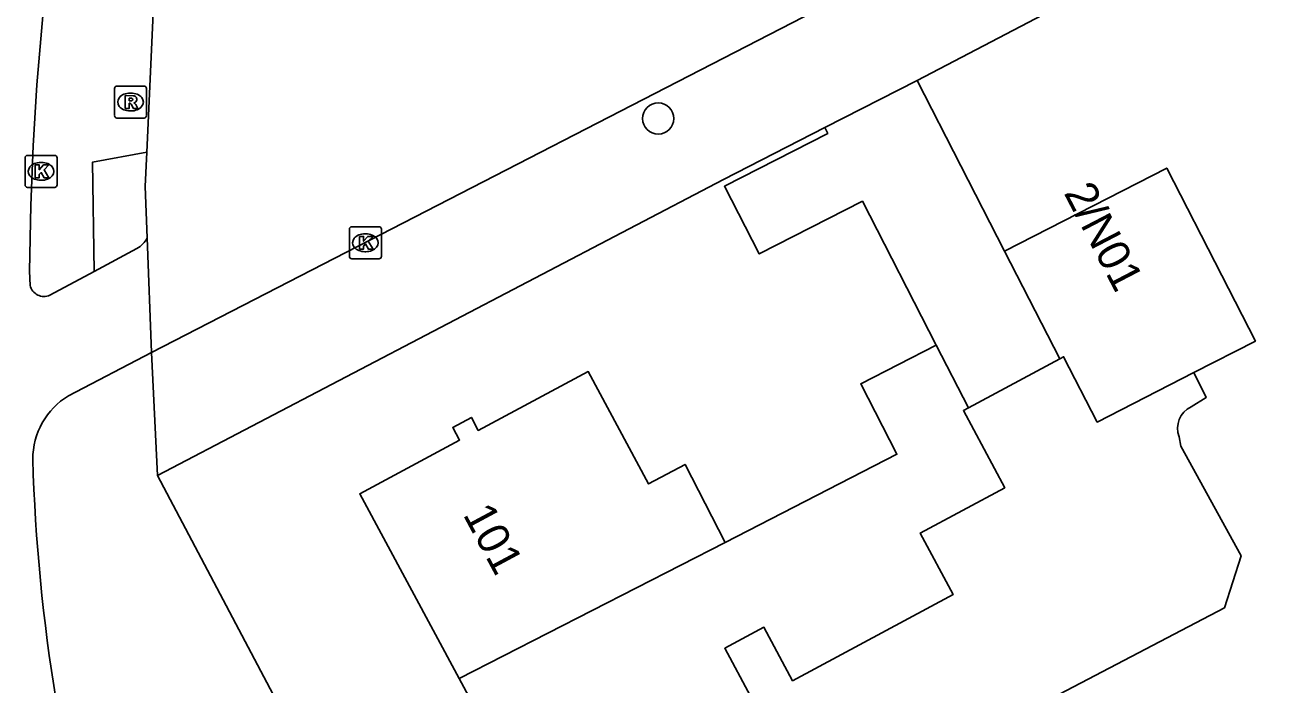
# Model space of a CAD drawing. Extents: x 162880 to 165536, y 384011 to 385179.
# Drawn here: x 162927.6 to 162966.79, y 384170.7 to 384191.34 of the extents above; entities that cross this region are included whole.
import ezdxf

# ---------------------------------------------------------------- set-up
doc = ezdxf.new("R2010")
doc.units = 0
for name, color, linetype in [('IMGEO_Boom', 7, 'Continuous'), ('IMGEO_Fietspad_open', 7, 'Continuous'), ('IMGEO_Groenvoorziening', 7, 'Continuous'), ('IMGEO_Kolk', 7, 'Continuous'), ('IMGEO_Pand', 7, 'Continuous'), ('IMGEO_Pand_nummerreeks', 7, 'Continuous'), ('IMGEO_Rijbaan_lokaal_open', 7, 'Continuous'), ('IMGEO_Rioolput', 7, 'Continuous'), ('IMGEO_Voetpad_open', 7, 'Continuous')]:
    doc.layers.add(name, color=color, linetype=linetype)

msp = doc.modelspace()

# ---------------------------------------------------------------- linework, layer by layer
at = {"layer": 'IMGEO_Boom'}
msp.add_circle((162947.388, 384188.412), 0.489, dxfattribs=at)
at = {"layer": 'IMGEO_Fietspad_open'}
for points in [[(162927.759, 384183.194), (162927.739, 384183.64), (162927.779, 384185.695), (162927.846, 384187.562), (162927.96, 384189.468), (162928.193, 384192.099)], [(162929.751, 384183.633), (162931.087, 384184.349)], [(162929.751, 384183.633), (162928.37, 384182.892)], [(162931.553, 384181.098), (162928.956, 384179.741)]]:
    msp.add_lwpolyline(points, dxfattribs=at)
for centre, radius, start, end in [((162930.781, 384184.976), 0.697, 296.0123, 335.3683), ((162928.181, 384183.279), 0.431, 191.4134, 295.9829), ((162930.134, 384177.77), 2.296, 120.8634, 180.4074), ((162984.182, 384179.392), 56.368, 181.6649, 197.079)]:
    msp.add_arc(centre, radius, start, end, dxfattribs=at)
at = {"layer": 'IMGEO_Groenvoorziening'}
for points in [[(162964.134, 384180.467), (162964.511, 384179.684), (162964.05, 384179.396)], [(162963.675, 384178.458), (162963.724, 384178.168), (162965.607, 384174.74), (162965.09, 384173.113), (162951.391, 384165.934), (162950.819, 384165.634), (162952.828, 384161.829), (162942.595, 384156.45)]]:
    msp.add_lwpolyline(points, dxfattribs=at)
msp.add_arc((162964.352, 384178.731), 0.73, 114.4429, 201.9753, dxfattribs=at)
at = {"layer": 'IMGEO_Kolk'}
for p, q in [((162927.596, 384186.334), (162927.596, 384187.186)), ((162927.671, 384187.26), (162928.523, 384187.26)), ((162928.597, 384187.186), (162928.597, 384186.334)), ((162928.084, 384187.04), (162928.109, 384187.04)), ((162928.107, 384186.48), (162928.082, 384186.48)), ((162928.523, 384186.26), (162927.671, 384186.26)), ((162937.734, 384184.102), (162937.734, 384184.954)), ((162937.809, 384185.028), (162938.661, 384185.028)), ((162938.222, 384184.808), (162938.247, 384184.808)), ((162938.735, 384184.954), (162938.735, 384184.102)), ((162938.661, 384184.028), (162937.809, 384184.028)), ((162938.245, 384184.248), (162938.22, 384184.248))]:
    msp.add_line(p, q, dxfattribs=at)
for points in [[(162927.596, 384186.334), (162927.596, 384187.186)], [(162927.671, 384187.26), (162928.523, 384187.26)], [(162928.597, 384187.186), (162928.597, 384186.334)], [(162927.917, 384186.96), (162928.04, 384186.96), (162928.04, 384186.809), (162928.17, 384186.96), (162928.334, 384186.96), (162928.188, 384186.809), (162928.341, 384186.56), (162928.189, 384186.56), (162928.104, 384186.724), (162928.04, 384186.657), (162928.04, 384186.56), (162927.917, 384186.56), (162927.917, 384186.96)], [(162928.523, 384186.26), (162927.671, 384186.26)], [(162937.734, 384184.102), (162937.734, 384184.954)], [(162937.809, 384185.028), (162938.661, 384185.028)], [(162938.735, 384184.954), (162938.735, 384184.102)], [(162938.055, 384184.728), (162938.178, 384184.728), (162938.178, 384184.577), (162938.308, 384184.728), (162938.472, 384184.728), (162938.326, 384184.577), (162938.479, 384184.328), (162938.327, 384184.328), (162938.242, 384184.492), (162938.178, 384184.425), (162938.178, 384184.328), (162938.055, 384184.328), (162938.055, 384184.728)], [(162938.661, 384184.028), (162937.809, 384184.028)]]:
    msp.add_lwpolyline(points, dxfattribs=at)
for centre, start, end in [((162927.673, 384187.184), 91.552, 178.448), ((162927.673, 384187.184), 91.552, 178.448), ((162928.521, 384187.184), 1.552, 88.448), ((162928.521, 384187.184), 1.552, 88.448), ((162927.673, 384186.336), 181.552, 268.448), ((162927.673, 384186.336), 181.552, 268.448), ((162928.521, 384186.336), 271.552, 358.448), ((162928.521, 384186.336), 271.552, 358.448), ((162937.811, 384184.952), 91.552, 178.448), ((162937.811, 384184.952), 91.552, 178.448), ((162938.659, 384184.952), 1.552, 88.448), ((162938.659, 384184.952), 1.552, 88.448), ((162937.811, 384184.104), 181.552, 268.448), ((162937.811, 384184.104), 181.552, 268.448), ((162938.659, 384184.104), 271.552, 358.448), ((162938.659, 384184.104), 271.552, 358.448)]:
    msp.add_arc(centre, 0.0765, start, end, dxfattribs=at)
for centre, major_axis, ratio, start_param, end_param in [((162928.083, 384186.76), (-0.387, 0.002), 0.722429, 4.712389, 7.853982), ((162928.108, 384186.76), (-0.39, 0.002), 0.717154, 1.570796, 4.712389), ((162938.221, 384184.528), (-0.387, 0.002), 0.722429, 4.712389, 7.853982), ((162938.246, 384184.528), (-0.39, 0.002), 0.717154, 1.570796, 4.712389)]:
    msp.add_ellipse(centre, major_axis=major_axis, ratio=ratio, start_param=start_param, end_param=end_param, dxfattribs=at)
at = {"layer": 'IMGEO_Pand'}
for points in [[(162952.594, 384188.127), (162955.477, 384189.605)], [(162955.477, 384189.605), (162958.214, 384184.265)], [(162952.594, 384188.127), (162952.685, 384187.949), (162949.459, 384186.296), (162950.545, 384184.176), (162953.772, 384185.828), (162956.078, 384181.328)], [(162958.214, 384184.265), (162963.283, 384186.864), (162965.008, 384183.5), (162966.057, 384181.453), (162964.134, 384180.467)], [(162959.939, 384180.899), (162958.214, 384184.265)], [(162949.476, 384175.158), (162954.851, 384177.912), (162953.72, 384180.119), (162956.078, 384181.328)], [(162956.078, 384181.328), (162957.085, 384179.365)], [(162957.085, 384179.365), (162959.939, 384180.899)], [(162964.134, 384180.467), (162961.109, 384178.917), (162960.06, 384180.964), (162959.939, 384180.899)], [(162941.166, 384170.898), (162938.06, 384176.678), (162941.178, 384178.354), (162940.965, 384178.751), (162941.547, 384179.063), (162941.764, 384178.657), (162945.201, 384180.5), (162947.086, 384176.985), (162948.226, 384177.596), (162949.476, 384175.158)], [(162957.085, 384179.365), (162956.925, 384179.279), (162958.221, 384176.868), (162955.578, 384175.448), (162956.61, 384173.527), (162951.589, 384170.83), (162950.69, 384172.503), (162949.466, 384171.845), (162951.077, 384168.848), (162944.242, 384165.175), (162941.166, 384170.898)], [(162941.166, 384170.898), (162949.476, 384175.158)]]:
    msp.add_lwpolyline(points, dxfattribs=at)
at = {"layer": 'IMGEO_Rijbaan_lokaal_open'}
for points in [[(162931.706, 384194.016), (162931.403, 384187.357)], [(162956.944, 384194.183), (162931.553, 384181.098)], [(162931.415, 384184.685), (162931.354, 384186.287), (162931.403, 384187.357)], [(162931.553, 384181.098), (162931.415, 384184.685)]]:
    msp.add_lwpolyline(points, dxfattribs=at)
at = {"layer": 'IMGEO_Rioolput'}
for p, q in [((162930.391, 384188.502), (162930.391, 384189.354)), ((162930.466, 384189.428), (162931.318, 384189.428)), ((162930.879, 384189.208), (162930.904, 384189.208)), ((162931.392, 384189.354), (162931.392, 384188.502)), ((162931.318, 384188.428), (162930.466, 384188.428)), ((162930.902, 384188.648), (162930.877, 384188.648))]:
    msp.add_line(p, q, dxfattribs=at)
for points in [[(162930.391, 384188.502), (162930.391, 384189.354)], [(162930.466, 384189.428), (162931.318, 384189.428)], [(162930.98, 384189.126), (162930.728, 384189.128), (162930.728, 384188.728)], [(162931.392, 384189.354), (162931.392, 384188.502)], [(162930.728, 384188.728), (162930.852, 384188.728), (162930.852, 384188.89), (162930.863, 384188.89)], [(162930.906, 384189.047), (162930.852, 384189.047), (162930.852, 384188.966)], [(162930.852, 384188.966), (162930.904, 384188.966)], [(162930.91, 384188.861), (162930.981, 384188.728), (162931.121, 384188.728), (162931.056, 384188.854)], [(162931.318, 384188.428), (162930.466, 384188.428)]]:
    msp.add_lwpolyline(points, dxfattribs=at)
for centre, radius, start, end in [((162930.468, 384189.352), 0.0765, 91.552, 178.448), ((162930.468, 384189.352), 0.0765, 91.552, 178.448), ((162930.979, 384189.016), 0.109, 350.3612, 89.416), ((162931.316, 384189.352), 0.0765, 1.552, 88.448), ((162931.316, 384189.352), 0.0765, 1.552, 88.448), ((162930.862, 384188.837), 0.0533, 26.0293, 88.6989), ((162930.888, 384189.155), 0.19, 274.7715, 282.9687), ((162930.912, 384188.951), 0.0964, 77.0061, 93.1865), ((162930.926, 384189.008), 0.0378, 276.6634, 79.6772), ((162930.977, 384189.016), 0.112, 277.5842, 350.9817), ((162930.961, 384188.801), 0.108, 29.5134, 73.7905), ((162930.468, 384188.504), 0.0765, 181.552, 268.448), ((162930.468, 384188.504), 0.0765, 181.552, 268.448), ((162931.316, 384188.504), 0.0765, 271.552, 358.448), ((162931.316, 384188.504), 0.0765, 271.552, 358.448)]:
    msp.add_arc(centre, radius, start, end, dxfattribs=at)
for centre, major_axis, ratio, start_param, end_param in [((162930.878, 384188.928), (-0.387, 0.002), 0.722429, 4.712389, 7.853982), ((162930.903, 384188.928), (-0.39, 0.002), 0.717154, 1.570796, 4.712389)]:
    msp.add_ellipse(centre, major_axis=major_axis, ratio=ratio, start_param=start_param, end_param=end_param, dxfattribs=at)
at = {"layer": 'IMGEO_Voetpad_open'}
for points in [[(162955.477, 384189.605), (162970.977, 384197.711)], [(162931.731, 384177.249), (162949.426, 384186.503), (162952.594, 384188.127)], [(162931.403, 384187.357), (162929.703, 384187.043), (162929.751, 384183.633)], [(162931.553, 384181.098), (162931.731, 384177.249)], [(162942.595, 384156.45), (162941.707, 384158.354), (162931.731, 384177.249)]]:
    msp.add_lwpolyline(points, dxfattribs=at)

# ---------------------------------------------------------------- texts
at = {"layer": 'IMGEO_Pand_nummerreeks'}
for s, rotation, p in [('2/N01', 297.5291, (162960.054, 384186.086)), ('101', 298.2532, (162941.27, 384176.03))]:
    msp.add_text(s, height=1, rotation=rotation, dxfattribs=at).set_placement(p)

doc.saveas('drawing.dxf')
